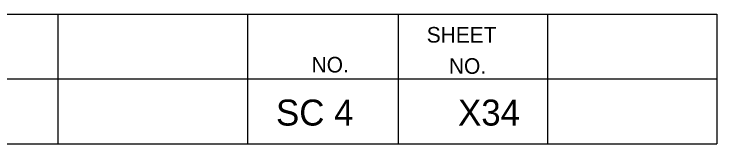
# Model space of a CAD drawing. Extents: x 1000 to 1162, y 999 to 8520.
# Drawn here: x 1148.08 to 1161.56, y 4895.05 to 4897.55 of the extents above; entities that cross this region are included whole.
import ezdxf

# ---------------------------------------------------------------- set-up
doc = ezdxf.new("R2010")
doc.units = 0
doc.layers.add('Level 20', color=7, linetype='Continuous')
doc.layers.add('Level 3', color=7, linetype='Continuous')

msp = doc.modelspace()

# ---------------------------------------------------------------- linework, layer by layer
at = {"layer": 'Level 3'}
for p, q in [((1133.055, 4897.546), (1161.555, 4897.546)), ((1133.055, 4897.546), (1161.555, 4897.546)), ((1133.055, 4897.546), (1161.555, 4897.546)), ((1133.055, 4897.546), (1161.555, 4897.546)), ((1133.055, 4897.546), (1161.555, 4897.546)), ((1133.055, 4897.546), (1161.555, 4897.546)), ((1133.055, 4897.546), (1161.555, 4897.546)), ((1133.055, 4897.546), (1161.555, 4897.546)), ((1133.055, 4897.546), (1161.555, 4897.546)), ((1133.055, 4897.546), (1161.555, 4897.546)), ((1133.055, 4897.546), (1161.555, 4897.546)), ((1133.055, 4897.546), (1161.555, 4897.546)), ((1133.055, 4897.546), (1161.555, 4897.546)), ((1133.055, 4897.546), (1161.555, 4897.546)), ((1133.055, 4897.546), (1161.555, 4897.546)), ((1133.055, 4897.546), (1161.555, 4897.546)), ((1133.055, 4897.546), (1161.555, 4897.546)), ((1133.055, 4897.546), (1161.555, 4897.546)), ((1133.055, 4897.546), (1161.555, 4897.546)), ((1133.055, 4897.546), (1161.555, 4897.546)), ((1133.055, 4897.546), (1161.555, 4897.546)), ((1133.055, 4897.546), (1161.555, 4897.546)), ((1133.055, 4897.546), (1161.555, 4897.546)), ((1133.055, 4897.546), (1161.555, 4897.546)), ((1133.055, 4897.546), (1161.555, 4897.546)), ((1133.055, 4897.546), (1161.555, 4897.546)), ((1133.055, 4897.546), (1161.555, 4897.546)), ((1133.055, 4897.546), (1161.555, 4897.546)), ((1133.055, 4897.546), (1161.555, 4897.546)), ((1133.055, 4897.546), (1161.555, 4897.546)), ((1133.055, 4897.546), (1161.555, 4897.546)), ((1133.055, 4897.546), (1161.555, 4897.546)), ((1148.913, 4897.546), (1148.913, 4895.046)), ((1148.913, 4897.546), (1148.913, 4895.046)), ((1148.913, 4897.546), (1148.913, 4895.046)), ((1148.913, 4897.546), (1148.913, 4895.046)), ((1148.913, 4897.546), (1148.913, 4895.046)), ((1148.913, 4897.546), (1148.913, 4895.046)), ((1148.913, 4897.546), (1148.913, 4895.046)), ((1148.913, 4897.546), (1148.913, 4895.046)), ((1148.913, 4897.546), (1148.913, 4895.046)), ((1148.913, 4897.546), (1148.913, 4895.046)), ((1148.913, 4897.546), (1148.913, 4895.046)), ((1148.913, 4897.546), (1148.913, 4895.046)), ((1148.913, 4897.546), (1148.913, 4895.046)), ((1148.913, 4897.546), (1148.913, 4895.046)), ((1148.913, 4897.546), (1148.913, 4895.046)), ((1148.913, 4897.546), (1148.913, 4895.046)), ((1148.913, 4897.546), (1148.913, 4895.046)), ((1148.913, 4897.546), (1148.913, 4895.046)), ((1148.913, 4897.546), (1148.913, 4895.046)), ((1148.913, 4897.546), (1148.913, 4895.046)), ((1148.913, 4897.546), (1148.913, 4895.046)), ((1148.913, 4897.546), (1148.913, 4895.046)), ((1148.913, 4897.546), (1148.913, 4895.046)), ((1148.913, 4897.546), (1148.913, 4895.046)), ((1148.913, 4897.546), (1148.913, 4895.046)), ((1148.913, 4897.546), (1148.913, 4895.046)), ((1148.913, 4897.546), (1148.913, 4895.046)), ((1148.913, 4897.546), (1148.913, 4895.046)), ((1148.913, 4897.546), (1148.913, 4895.046)), ((1148.913, 4897.546), (1148.913, 4895.046)), ((1148.913, 4897.546), (1148.913, 4895.046)), ((1148.913, 4897.546), (1148.913, 4895.046)), ((1152.554, 4897.546), (1152.554, 4895.046)), ((1152.554, 4897.546), (1152.554, 4895.046)), ((1152.554, 4897.546), (1152.554, 4895.046)), ((1152.554, 4897.546), (1152.554, 4895.046)), ((1152.554, 4897.546), (1152.554, 4895.046)), ((1152.554, 4897.546), (1152.554, 4895.046)), ((1152.554, 4897.546), (1152.554, 4895.046)), ((1152.554, 4897.546), (1152.554, 4895.046)), ((1152.554, 4897.546), (1152.554, 4895.046)), ((1152.554, 4897.546), (1152.554, 4895.046)), ((1152.554, 4897.546), (1152.554, 4895.046)), ((1152.554, 4897.546), (1152.554, 4895.046)), ((1152.554, 4897.546), (1152.554, 4895.046)), ((1152.554, 4897.546), (1152.554, 4895.046)), ((1152.554, 4897.546), (1152.554, 4895.046)), ((1152.554, 4897.546), (1152.554, 4895.046)), ((1152.554, 4897.546), (1152.554, 4895.046)), ((1152.554, 4897.546), (1152.554, 4895.046)), ((1152.554, 4897.546), (1152.554, 4895.046)), ((1152.554, 4897.546), (1152.554, 4895.046)), ((1152.554, 4897.546), (1152.554, 4895.046)), ((1152.554, 4897.546), (1152.554, 4895.046)), ((1152.554, 4897.546), (1152.554, 4895.046)), ((1152.554, 4897.546), (1152.554, 4895.046)), ((1152.554, 4897.546), (1152.554, 4895.046)), ((1152.554, 4897.546), (1152.554, 4895.046)), ((1152.554, 4897.546), (1152.554, 4895.046)), ((1152.554, 4897.546), (1152.554, 4895.046)), ((1152.554, 4897.546), (1152.554, 4895.046)), ((1152.554, 4897.546), (1152.554, 4895.046)), ((1152.554, 4897.546), (1152.554, 4895.046)), ((1152.554, 4897.546), (1152.554, 4895.046)), ((1155.44, 4897.546), (1155.44, 4895.046)), ((1155.44, 4897.546), (1155.44, 4895.046)), ((1155.44, 4897.546), (1155.44, 4895.046)), ((1155.44, 4897.546), (1155.44, 4895.046)), ((1155.44, 4897.546), (1155.44, 4895.046)), ((1155.44, 4897.546), (1155.44, 4895.046)), ((1155.44, 4897.546), (1155.44, 4895.046)), ((1155.44, 4897.546), (1155.44, 4895.046)), ((1155.44, 4897.546), (1155.44, 4895.046)), ((1155.44, 4897.546), (1155.44, 4895.046)), ((1155.44, 4897.546), (1155.44, 4895.046)), ((1155.44, 4897.546), (1155.44, 4895.046)), ((1155.44, 4897.546), (1155.44, 4895.046)), ((1155.44, 4897.546), (1155.44, 4895.046)), ((1155.44, 4897.546), (1155.44, 4895.046)), ((1155.44, 4897.546), (1155.44, 4895.046)), ((1155.44, 4897.546), (1155.44, 4895.046)), ((1155.44, 4897.546), (1155.44, 4895.046)), ((1155.44, 4897.546), (1155.44, 4895.046)), ((1155.44, 4897.546), (1155.44, 4895.046)), ((1155.44, 4897.546), (1155.44, 4895.046)), ((1155.44, 4897.546), (1155.44, 4895.046)), ((1155.44, 4897.546), (1155.44, 4895.046)), ((1155.44, 4897.546), (1155.44, 4895.046)), ((1155.44, 4897.546), (1155.44, 4895.046)), ((1155.44, 4897.546), (1155.44, 4895.046)), ((1155.44, 4897.546), (1155.44, 4895.046)), ((1155.44, 4897.546), (1155.44, 4895.046)), ((1155.44, 4897.546), (1155.44, 4895.046)), ((1155.44, 4897.546), (1155.44, 4895.046)), ((1155.44, 4897.546), (1155.44, 4895.046)), ((1155.44, 4897.546), (1155.44, 4895.046)), ((1158.305, 4897.546), (1158.305, 4895.046)), ((1158.305, 4897.546), (1158.305, 4895.046)), ((1158.305, 4897.546), (1158.305, 4895.046)), ((1158.305, 4897.546), (1158.305, 4895.046)), ((1158.305, 4897.546), (1158.305, 4895.046)), ((1158.305, 4897.546), (1158.305, 4895.046)), ((1158.305, 4897.546), (1158.305, 4895.046)), ((1158.305, 4897.546), (1158.305, 4895.046)), ((1158.305, 4897.546), (1158.305, 4895.046)), ((1158.305, 4897.546), (1158.305, 4895.046)), ((1158.305, 4897.546), (1158.305, 4895.046)), ((1158.305, 4897.546), (1158.305, 4895.046)), ((1158.305, 4897.546), (1158.305, 4895.046)), ((1158.305, 4897.546), (1158.305, 4895.046)), ((1158.305, 4897.546), (1158.305, 4895.046)), ((1158.305, 4897.546), (1158.305, 4895.046)), ((1158.305, 4897.546), (1158.305, 4895.046)), ((1158.305, 4897.546), (1158.305, 4895.046)), ((1158.305, 4897.546), (1158.305, 4895.046)), ((1158.305, 4897.546), (1158.305, 4895.046)), ((1158.305, 4897.546), (1158.305, 4895.046)), ((1158.305, 4897.546), (1158.305, 4895.046)), ((1158.305, 4897.546), (1158.305, 4895.046)), ((1158.305, 4897.546), (1158.305, 4895.046)), ((1158.305, 4897.546), (1158.305, 4895.046)), ((1158.305, 4897.546), (1158.305, 4895.046)), ((1158.305, 4897.546), (1158.305, 4895.046)), ((1158.305, 4897.546), (1158.305, 4895.046)), ((1158.305, 4897.546), (1158.305, 4895.046)), ((1158.305, 4897.546), (1158.305, 4895.046)), ((1158.305, 4897.546), (1158.305, 4895.046)), ((1158.305, 4897.546), (1158.305, 4895.046)), ((1161.555, 4897.546), (1161.555, 4895.046)), ((1161.555, 4897.546), (1161.555, 4895.046)), ((1161.555, 4897.546), (1161.555, 4895.046)), ((1161.555, 4897.546), (1161.555, 4895.046)), ((1161.555, 4897.546), (1161.555, 4895.046)), ((1161.555, 4897.546), (1161.555, 4895.046)), ((1161.555, 4897.546), (1161.555, 4895.046)), ((1161.555, 4897.546), (1161.555, 4895.046)), ((1161.555, 4897.546), (1161.555, 4895.046)), ((1161.555, 4897.546), (1161.555, 4895.046)), ((1161.555, 4897.546), (1161.555, 4895.046)), ((1161.555, 4897.546), (1161.555, 4895.046)), ((1161.555, 4897.546), (1161.555, 4895.046)), ((1161.555, 4897.546), (1161.555, 4895.046)), ((1161.555, 4897.546), (1161.555, 4895.046)), ((1161.555, 4897.546), (1161.555, 4895.046)), ((1161.555, 4897.546), (1161.555, 4895.046)), ((1161.555, 4897.546), (1161.555, 4895.046)), ((1161.555, 4897.546), (1161.555, 4895.046)), ((1161.555, 4897.546), (1161.555, 4895.046)), ((1161.555, 4897.546), (1161.555, 4895.046)), ((1161.555, 4897.546), (1161.555, 4895.046)), ((1161.555, 4897.546), (1161.555, 4895.046)), ((1161.555, 4897.546), (1161.555, 4895.046)), ((1161.555, 4897.546), (1161.555, 4895.046)), ((1161.555, 4897.546), (1161.555, 4895.046)), ((1161.555, 4897.546), (1161.555, 4895.046)), ((1161.555, 4897.546), (1161.555, 4895.046)), ((1161.555, 4897.546), (1161.555, 4895.046)), ((1161.555, 4897.546), (1161.555, 4895.046)), ((1161.555, 4897.546), (1161.555, 4895.046)), ((1161.555, 4897.546), (1161.555, 4895.046)), ((1133.055, 4896.296), (1161.555, 4896.296)), ((1133.055, 4896.296), (1161.555, 4896.296)), ((1133.055, 4896.296), (1161.555, 4896.296)), ((1133.055, 4896.296), (1161.555, 4896.296)), ((1133.055, 4896.296), (1161.555, 4896.296)), ((1133.055, 4896.296), (1161.555, 4896.296)), ((1133.055, 4896.296), (1161.555, 4896.296)), ((1133.055, 4896.296), (1161.555, 4896.296)), ((1133.055, 4896.296), (1161.555, 4896.296)), ((1133.055, 4896.296), (1161.555, 4896.296)), ((1133.055, 4896.296), (1161.555, 4896.296)), ((1133.055, 4896.296), (1161.555, 4896.296)), ((1133.055, 4896.296), (1161.555, 4896.296)), ((1133.055, 4896.296), (1161.555, 4896.296)), ((1133.055, 4896.296), (1161.555, 4896.296)), ((1133.055, 4896.296), (1161.555, 4896.296)), ((1133.055, 4896.296), (1161.555, 4896.296)), ((1133.055, 4896.296), (1161.555, 4896.296)), ((1133.055, 4896.296), (1161.555, 4896.296)), ((1133.055, 4896.296), (1161.555, 4896.296)), ((1133.055, 4896.296), (1161.555, 4896.296)), ((1133.055, 4896.296), (1161.555, 4896.296)), ((1133.055, 4896.296), (1161.555, 4896.296)), ((1133.055, 4896.296), (1161.555, 4896.296)), ((1133.055, 4896.296), (1161.555, 4896.296)), ((1133.055, 4896.296), (1161.555, 4896.296)), ((1133.055, 4896.296), (1161.555, 4896.296)), ((1133.055, 4896.296), (1161.555, 4896.296)), ((1133.055, 4896.296), (1161.555, 4896.296)), ((1133.055, 4896.296), (1161.555, 4896.296)), ((1133.055, 4896.296), (1161.555, 4896.296)), ((1133.055, 4896.296), (1161.555, 4896.296)), ((1133.055, 4895.046), (1161.555, 4895.046)), ((1133.055, 4895.046), (1161.555, 4895.046)), ((1133.055, 4895.046), (1161.555, 4895.046)), ((1133.055, 4895.046), (1161.555, 4895.046)), ((1133.055, 4895.046), (1161.555, 4895.046)), ((1133.055, 4895.046), (1161.555, 4895.046)), ((1133.055, 4895.046), (1161.555, 4895.046)), ((1133.055, 4895.046), (1161.555, 4895.046)), ((1133.055, 4895.046), (1161.555, 4895.046)), ((1133.055, 4895.046), (1161.555, 4895.046)), ((1133.055, 4895.046), (1161.555, 4895.046)), ((1133.055, 4895.046), (1161.555, 4895.046)), ((1133.055, 4895.046), (1161.555, 4895.046)), ((1133.055, 4895.046), (1161.555, 4895.046)), ((1133.055, 4895.046), (1161.555, 4895.046)), ((1133.055, 4895.046), (1161.555, 4895.046)), ((1133.055, 4895.046), (1161.555, 4895.046)), ((1133.055, 4895.046), (1161.555, 4895.046)), ((1133.055, 4895.046), (1161.555, 4895.046)), ((1133.055, 4895.046), (1161.555, 4895.046)), ((1133.055, 4895.046), (1161.555, 4895.046)), ((1133.055, 4895.046), (1161.555, 4895.046)), ((1133.055, 4895.046), (1161.555, 4895.046)), ((1133.055, 4895.046), (1161.555, 4895.046)), ((1133.055, 4895.046), (1161.555, 4895.046)), ((1133.055, 4895.046), (1161.555, 4895.046)), ((1133.055, 4895.046), (1161.555, 4895.046)), ((1133.055, 4895.046), (1161.555, 4895.046)), ((1133.055, 4895.046), (1161.555, 4895.046)), ((1133.055, 4895.046), (1161.555, 4895.046)), ((1133.055, 4895.046), (1161.555, 4895.046)), ((1133.055, 4895.046), (1161.555, 4895.046))]:
    msp.add_line(p, q, dxfattribs=at)

# ---------------------------------------------------------------- texts
at = {"layer": 'Level 20'}
for s, p in [('SC 4', (1153.099, 4895.4)), ('X34', (1156.59, 4895.4))]:
    msp.add_text(s, height=0.5, dxfattribs=at).set_placement(p)
at = {"layer": 'Level 3'}
for s, p in [('SHEET', (1155.99, 4896.996)), ('SHEET', (1155.99, 4896.996)), ('SHEET', (1155.99, 4896.996)), ('SHEET', (1155.99, 4896.996)), ('SHEET', (1155.99, 4896.996)), ('SHEET', (1155.99, 4896.996)), ('SHEET', (1155.99, 4896.996)), ('SHEET', (1155.99, 4896.996)), ('SHEET', (1155.99, 4896.996)), ('SHEET', (1155.99, 4896.996)), ('SHEET', (1155.99, 4896.996)), ('SHEET', (1155.99, 4896.996)), ('SHEET', (1155.99, 4896.996)), ('SHEET', (1155.99, 4896.996)), ('SHEET', (1155.99, 4896.996)), ('SHEET', (1155.99, 4896.996)), ('SHEET', (1155.99, 4896.996)), ('SHEET', (1155.99, 4896.996)), ('SHEET', (1155.99, 4896.996)), ('SHEET', (1155.99, 4896.996)), ('SHEET', (1155.99, 4896.996)), ('SHEET', (1155.99, 4896.996)), ('SHEET', (1155.99, 4896.996)), ('SHEET', (1155.99, 4896.996)), ('SHEET', (1155.99, 4896.996)), ('SHEET', (1155.99, 4896.996)), ('SHEET', (1155.99, 4896.996)), ('SHEET', (1155.99, 4896.996)), ('SHEET', (1155.99, 4896.996)), ('SHEET', (1155.99, 4896.996)), ('SHEET', (1155.99, 4896.996)), ('SHEET', (1155.99, 4896.996)), ('NO.', (1153.782, 4896.421)), ('NO.', (1153.782, 4896.421)), ('NO.', (1153.782, 4896.421)), ('NO.', (1153.782, 4896.421)), ('NO.', (1153.782, 4896.421)), ('NO.', (1153.782, 4896.421)), ('NO.', (1153.782, 4896.421)), ('NO.', (1153.782, 4896.421)), ('NO.', (1153.782, 4896.421)), ('NO.', (1153.782, 4896.421)), ('NO.', (1153.782, 4896.421)), ('NO.', (1153.782, 4896.421)), ('NO.', (1153.782, 4896.421)), ('NO.', (1153.782, 4896.421)), ('NO.', (1153.782, 4896.421)), ('NO.', (1153.782, 4896.421)), ('NO.', (1153.782, 4896.421)), ('NO.', (1153.782, 4896.421)), ('NO.', (1153.782, 4896.421)), ('NO.', (1153.782, 4896.421)), ('NO.', (1153.782, 4896.421)), ('NO.', (1153.782, 4896.421)), ('NO.', (1153.782, 4896.421)), ('NO.', (1153.782, 4896.421)), ('NO.', (1153.782, 4896.421)), ('NO.', (1153.782, 4896.421)), ('NO.', (1153.782, 4896.421)), ('NO.', (1153.782, 4896.421)), ('NO.', (1153.782, 4896.421)), ('NO.', (1153.782, 4896.421)), ('NO.', (1153.782, 4896.421)), ('NO.', (1153.782, 4896.421)), ('NO.', (1156.415, 4896.396)), ('NO.', (1156.415, 4896.396)), ('NO.', (1156.415, 4896.396)), ('NO.', (1156.415, 4896.396)), ('NO.', (1156.415, 4896.396)), ('NO.', (1156.415, 4896.396)), ('NO.', (1156.415, 4896.396)), ('NO.', (1156.415, 4896.396)), ('NO.', (1156.415, 4896.396)), ('NO.', (1156.415, 4896.396)), ('NO.', (1156.415, 4896.396)), ('NO.', (1156.415, 4896.396)), ('NO.', (1156.415, 4896.396)), ('NO.', (1156.415, 4896.396)), ('NO.', (1156.415, 4896.396)), ('NO.', (1156.415, 4896.396)), ('NO.', (1156.415, 4896.396)), ('NO.', (1156.415, 4896.396)), ('NO.', (1156.415, 4896.396)), ('NO.', (1156.415, 4896.396)), ('NO.', (1156.415, 4896.396)), ('NO.', (1156.415, 4896.396)), ('NO.', (1156.415, 4896.396)), ('NO.', (1156.415, 4896.396)), ('NO.', (1156.415, 4896.396)), ('NO.', (1156.415, 4896.396)), ('NO.', (1156.415, 4896.396)), ('NO.', (1156.415, 4896.396)), ('NO.', (1156.415, 4896.396)), ('NO.', (1156.415, 4896.396)), ('NO.', (1156.415, 4896.396)), ('NO.', (1156.415, 4896.396))]:
    msp.add_text(s, height=0.3, dxfattribs=at).set_placement(p)

doc.saveas('drawing.dxf')
